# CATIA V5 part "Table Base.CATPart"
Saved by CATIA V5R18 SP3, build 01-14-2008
Part number: Table
Bounding box of the stored display mesh (mm): x -135 to 135, y -800 to 800, z -58 to 0
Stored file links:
  E:\#00 CATIA V5 Movie\#03 CATIA V5 Data\#07 KIN\Balance Unit (1)\Table Base.CATPart
  Product1.CATProduct
  D:\#1000 Disk01\Work02\ACE\SA RR GLASS CENTERING UNIT\SA DG CV3011.CATPart
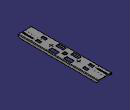
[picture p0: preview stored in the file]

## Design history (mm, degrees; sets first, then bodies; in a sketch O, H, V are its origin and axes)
Body1 "PartBody" (main body)
  Solid1: solid without history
